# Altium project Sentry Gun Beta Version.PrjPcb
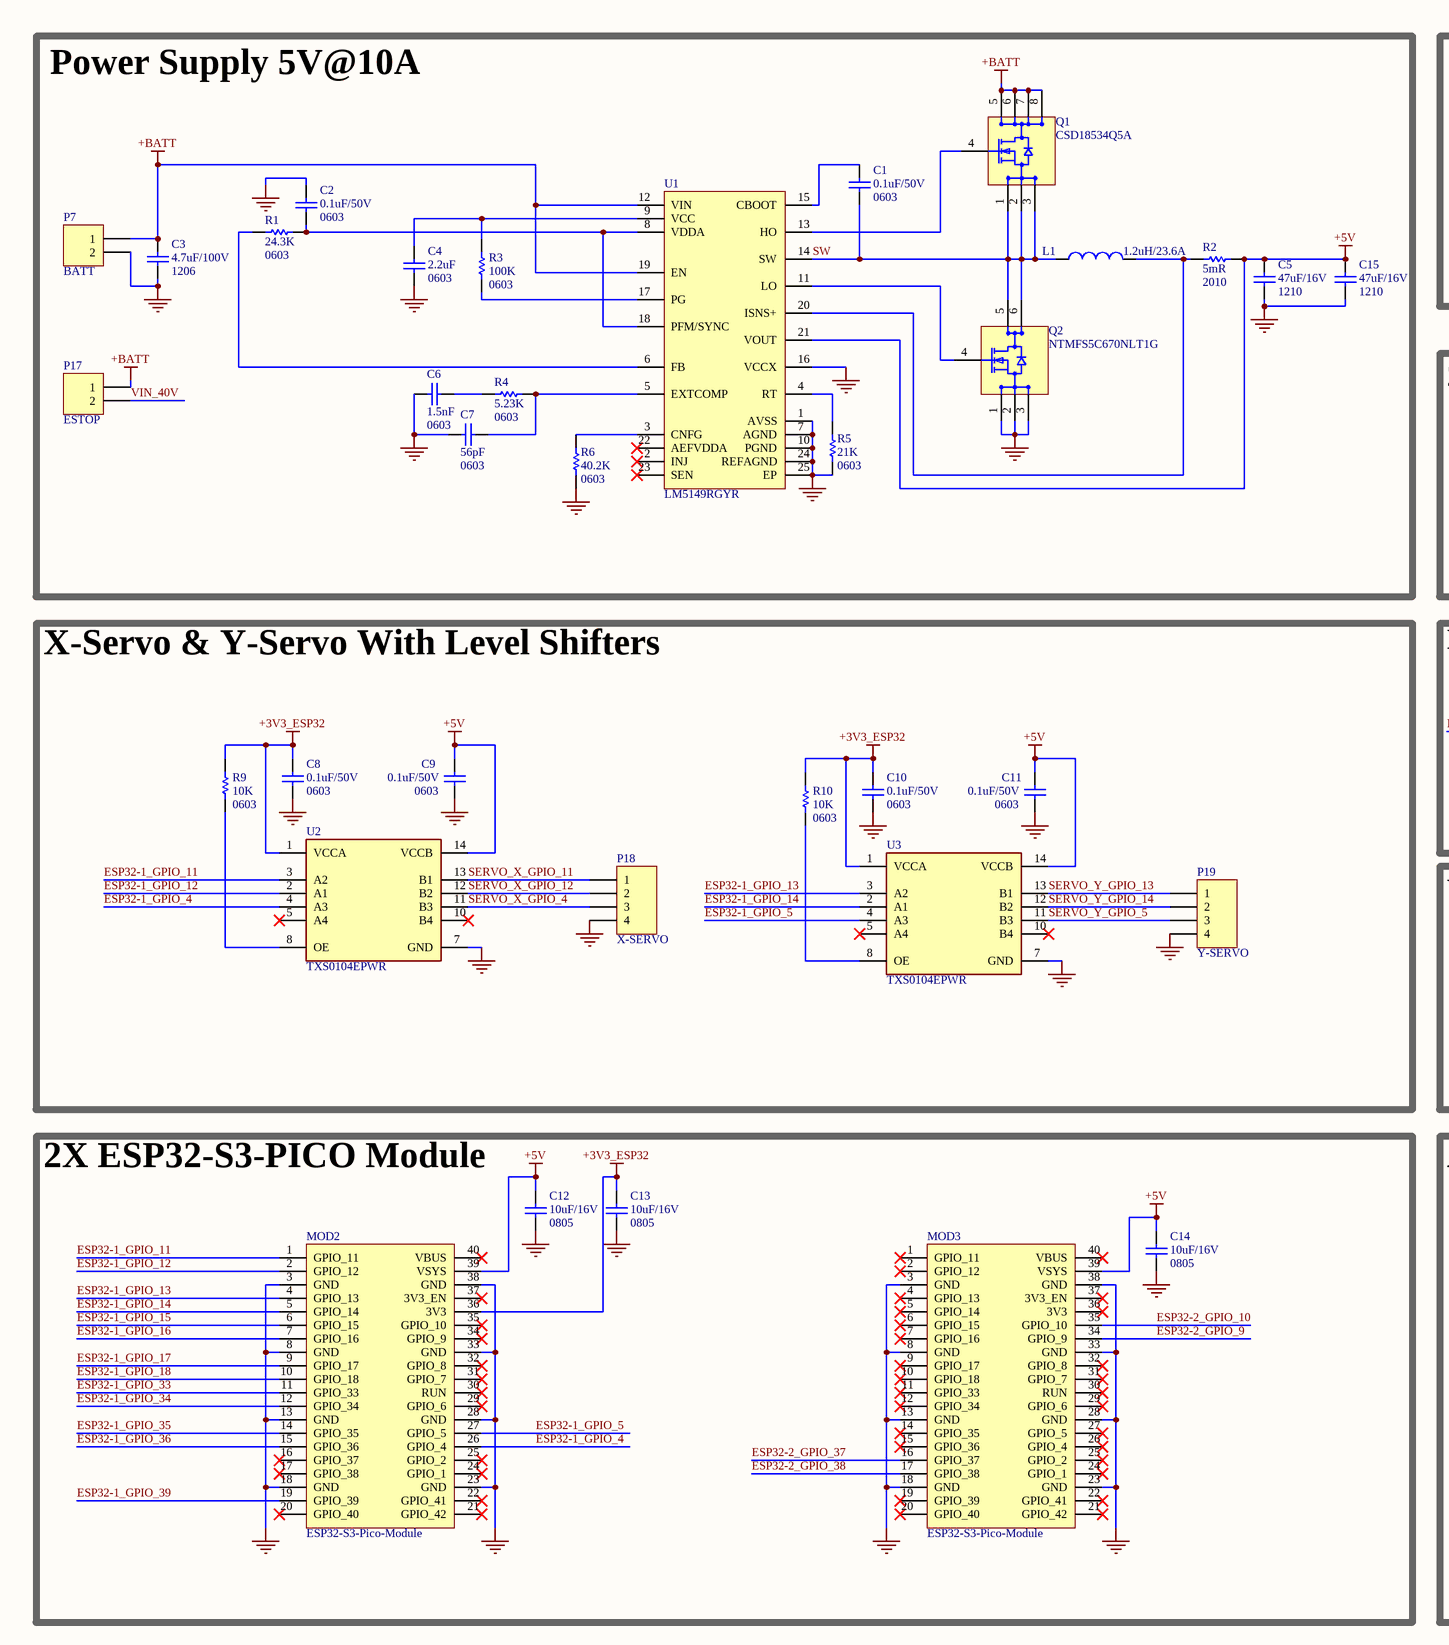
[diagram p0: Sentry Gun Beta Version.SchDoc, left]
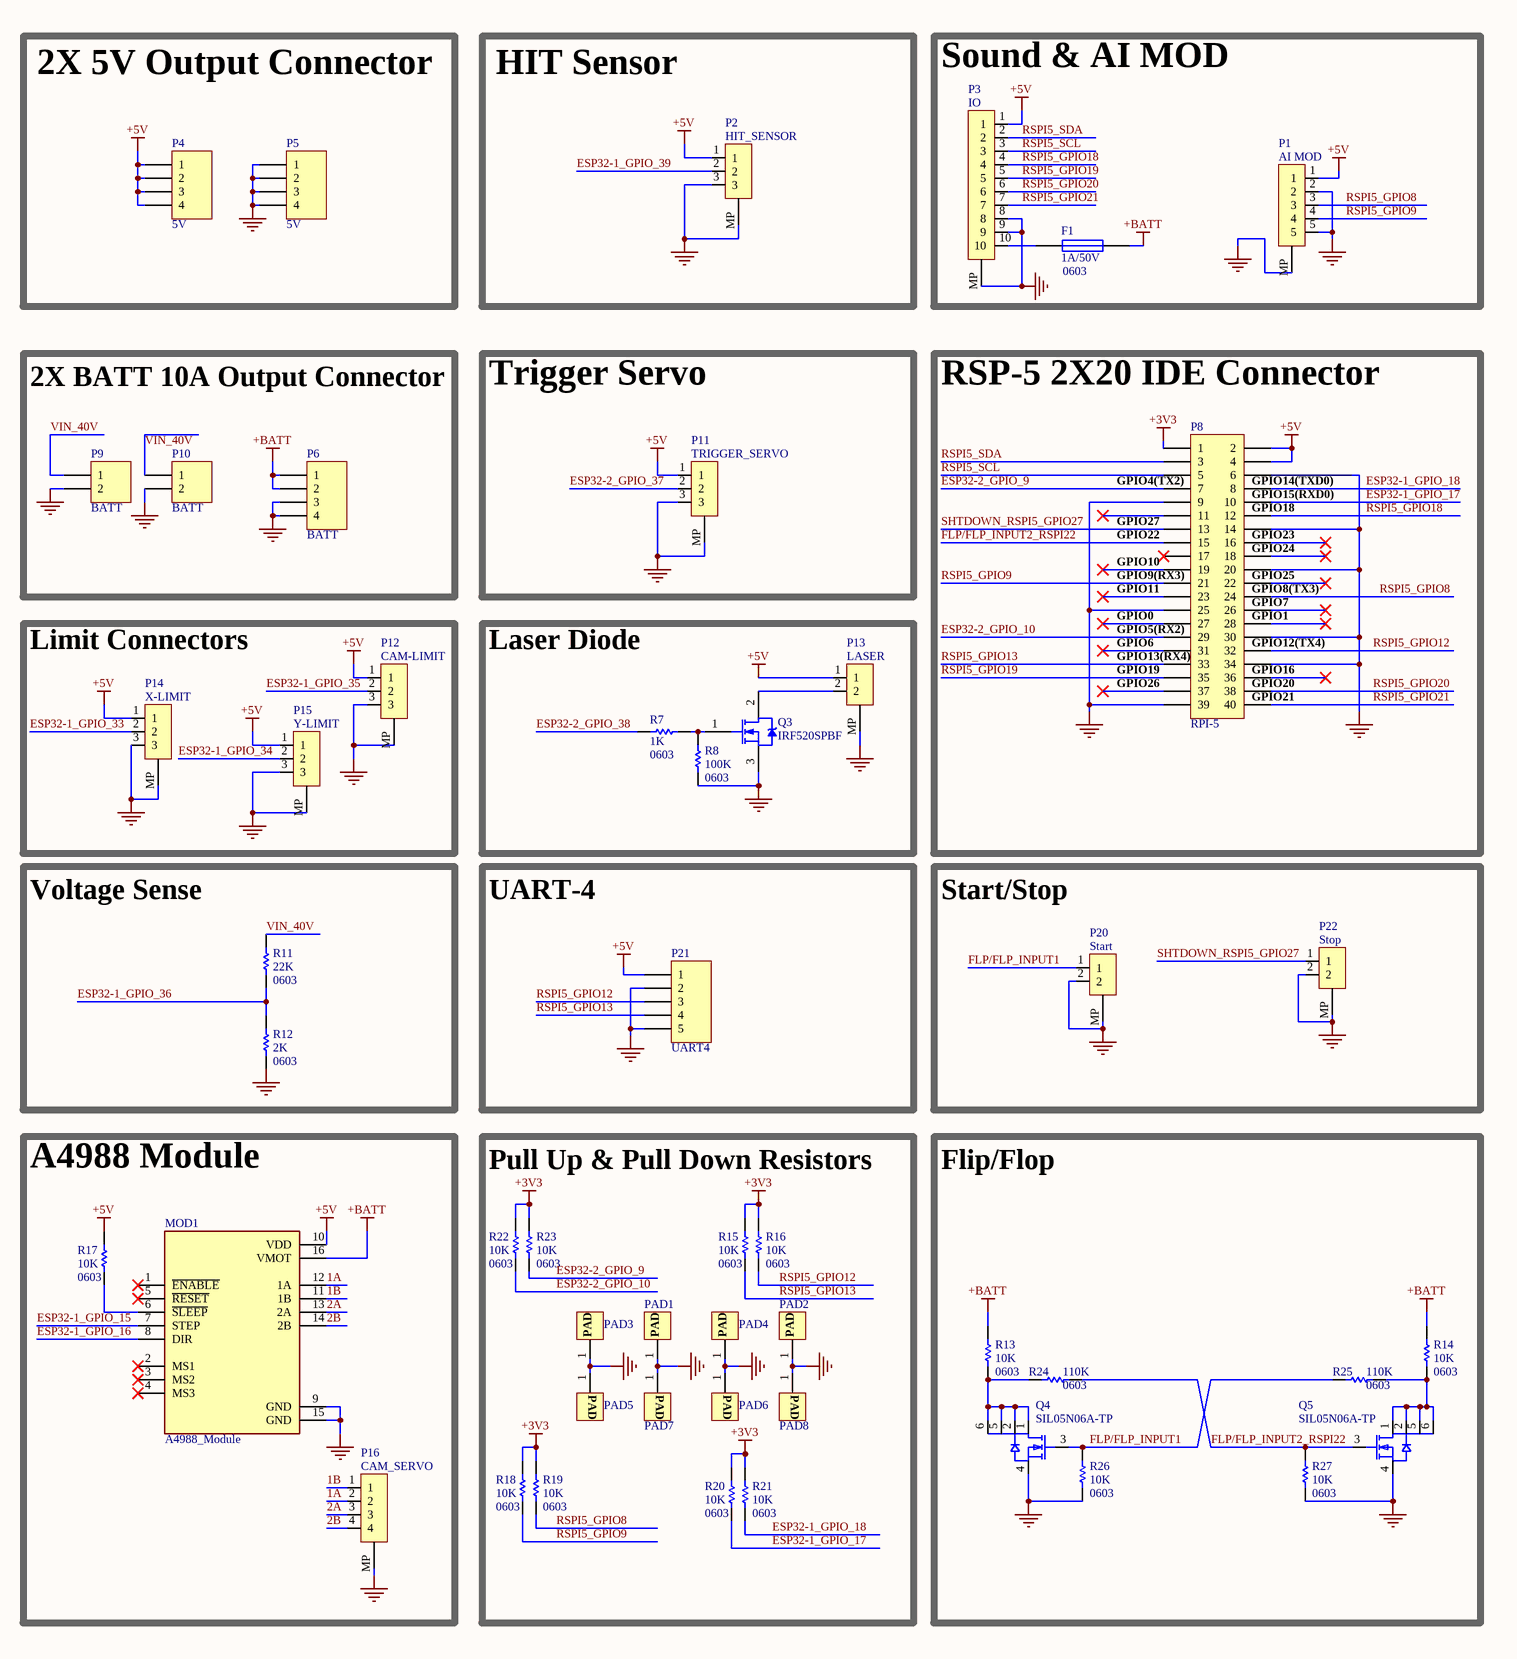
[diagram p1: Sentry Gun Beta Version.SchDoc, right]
1 sheet, 85 parts. Net scope: global (net labels, ports and power ports of the same name join across sheets).
Board file: PCB.PcbDoc

## Sheet Sentry Gun Beta Version.SchDoc
size A2; DocumentNumber: 0; SheetNumber: 0; SheetTotal: 7

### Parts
C1  0.1uF/50V  Package: 0603  [CAP_SMD_0603]
C2  0.1uF/50V  Package: 0603  [CAP_SMD_0603]
C3  4.7uF/100V  Package: 1206  [CAP_SMD_1206]
C4  2.2uF  Package: 0603  [CAP_SMD_0603]
C5  47uF/16V  Package: 1210  [CAP_SMD_1210]
C6  1.5nF  Package: 0603  [CAP_SMD_0603]
C7  56pF  Package: 0603  [CAP_SMD_0603]
C8  0.1uF/50V  Package: 0603  [CAP_SMD_0603]
C9  0.1uF/50V  Package: 0603  [CAP_SMD_0603]
C10  0.1uF/50V  Package: 0603  [CAP_SMD_0603]
C11  0.1uF/50V  Package: 0603  [CAP_SMD_0603]
C12  10uF/16V  Package: 0805  [CAP_SMD_0805]
C13  10uF/16V  Package: 0805  [CAP_SMD_0805]
C14  10uF/16V  Package: 0805  [CAP_SMD_0805]
C15  47uF/16V  Package: 1210  [CAP_SMD_1210]
F1  1A/50V  Package: 0603  [FUSE_SMD_0603]
L1  1.2uH/23.6A  [IND_SMD_7.90mm x 7.60mm]
MOD1  A4988_Module  [A4988_Stepper_Motor_Module]
MOD2  ESP32-S3-Pico-Module  [ESP32-S3-PICO_Module]
MOD3  ESP32-S3-Pico-Module  [ESP32-S3-PICO_Module]
P1  AI MOD  [CONN_Header_SMD_Vertical_5P_2MM_B5B-PH-SM4-TB]
P2  HIT_SENSOR  [CONN_Header_SMD_Vertical_3P_2MM_B3B-PH-SM4-TB]
P3  IO  [CONN_Header_SMD_Vertical_10P_2MM_B10B-PH-SM4-TB]
P4  5V  [CONN_Terminal_Block_Header_4P_Vertical__THT_5.00mm_1755532]
P5  5V  [CONN_Terminal_Block_Header_4P_Vertical__THT_5.00mm_1755532]
P6  BATT  [CONN_Terminal_Block_Header_4P_Vertical__THT_5.00mm_1755532]
P7  BATT  [CONN_HEADER_VERT_2POS_5MM_1-1376382-2]
P8  RPI-5  [CONN_HEADERTHT_IDE_40P_2.54mm]
P9  BATT  [CONN_HEADER_VERT_2POS_5MM_2-1376382-3]
P10  BATT  [CONN_HEADER_VERT_2POS_5MM_2-1376382-3]
P11  TRIGGER_SERVO  [CONN_Header_SMD_Vertical_3P_2MM_B3B-PH-SM4-TB]
P12  CAM-LIMIT  [CONN_Header_SMD_Vertical_3P_2MM_B3B-PH-SM4-TB]
P13  LASER  [CONN_Header_SMD_Vertical_2P_2MM_B2B-PH-SM4-TB]
P14  X-LIMIT  [CONN_Header_SMD_Vertical_3P_2MM_B3B-PH-SM4-TB]
P15  Y-LIMIT  [CONN_Header_SMD_Vertical_3P_2MM_B3B-PH-SM4-TB]
P16  CAM_SERVO  [CONN_Header_SMD_Vertical_4P_2MM_B4B-PH-SM4-TB]
P17  ESTOP  [CONN_HEADER_VERT_2POS_5MM_1-1376382-2]
P18  X-SERVO  [CONN_Header_Through_Hole_4P_2MM_B4B-PH-K]
P19  Y-SERVO  [CONN_Header_Through_Hole_4P_2MM_B4B-PH-K]
P20  Start  [CONN_Header_SMD_Vertical_2P_2MM_B2B-PH-SM4-TB]
P21  UART4  [CONN_Header_SMD_Vertical_5P_2MM_B5B-PH-SM4-TB]
P22  Stop  [CONN_Header_SMD_Vertical_2P_2MM_B2B-PH-SM4-TB]
PAD1  PAD  [PAD_SMD_0.8MMX0.9MM]  (value not drawn)
PAD2  PAD  [PAD_SMD_0.8MMX0.9MM]  (value not drawn)
PAD3  PAD  [PAD_SMD_0.8MMX0.9MM]  (value not drawn)
PAD4  PAD  [PAD_SMD_0.8MMX0.9MM]  (value not drawn)
PAD5  PAD  [PAD_SMD_0.8MMX0.9MM]  (value not drawn)
PAD6  PAD  [PAD_SMD_0.8MMX0.9MM]  (value not drawn)
PAD7  PAD  [PAD_SMD_0.8MMX0.9MM]  (value not drawn)
PAD8  PAD  [PAD_SMD_0.8MMX0.9MM]  (value not drawn)
Q1  CSD18534Q5A  [VSONP-8_5MMx6MM]
Q2  NTMFS5C670NLT1G  [DFN-5_5MMx6MM]
Q3  IRF520SPBF  [D2PAK]
Q4  SIL05N06A-TP  [SOT-23-6]
Q5  SIL05N06A-TP  [SOT-23-6]
R1  24.3K  Package: 0603  [RES_SMD_0603]
R2  5mR  Package: 2010  [RES_SMD_2010]
R3  100K  Package: 0603  [RES_SMD_0603]
R4  5.23K  Package: 0603  [RES_SMD_0603]
R5  21K  Package: 0603  [RES_SMD_0603]
R6  40.2K  Package: 0603  [RES_SMD_0603]
R7  1K  Package: 0603  [RES_SMD_0603]
R8  100K  Package: 0603  [RES_SMD_0603]
R9  10K  Package: 0603  [RES_SMD_0603]
R10  10K  Package: 0603  [RES_SMD_0603]
R11  22K  Package: 0603  [RES_SMD_0603]
R12  2K  Package: 0603  [RES_SMD_0603]
R13  10K  Package: 0603  [RES_SMD_0603]
R14  10K  Package: 0603  [RES_SMD_0603]
R15  10K  Package: 0603  [RES_SMD_0603]
R16  10K  Package: 0603  [RES_SMD_0603]
R17  10K  Package: 0603  [RES_SMD_0603]
R18  10K  Package: 0603  [RES_SMD_0603]
R19  10K  Package: 0603  [RES_SMD_0603]
R20  10K  Package: 0603  [RES_SMD_0603]
R21  10K  Package: 0603  [RES_SMD_0603]
R22  10K  Package: 0603  [RES_SMD_0603]
R23  10K  Package: 0603  [RES_SMD_0603]
R24  110K  Package: 0603  [RES_SMD_0603]
R25  110K  Package: 0603  [RES_SMD_0603]
R26  10K  Package: 0603  [RES_SMD_0603]
R27  10K  Package: 0603  [RES_SMD_0603]
U1  LM5149RGYR  [VQFN-24_3.5MMx5.5MM]
U2  TXS0104EPWR  [TSSOP-14]
U3  TXS0104EPWR  [TSSOP-14]

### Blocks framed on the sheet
Power Supply 5V@10A: C1-C7 C15 L1 P7 P17 Q1 Q2 R1-R6 U1
2X 5V Output Connector: P4 P5
HIT Sensor: P2
Sound & AI MOD: F1 P1 P3
2X BATT 10A Output Connector: P6 P9 P10
Trigger Servo: P11
RSP-5 2X20 IDE Connector: P8
X-Servo & Y-Servo With Level Shifters: C8-C11 P18 P19 R9 R10 U2 U3
Limit Connectors: P12 P14 P15
Laser Diode: P13 Q3 R7 R8
Voltage Sense: R11 R12
UART-4: P21
Start/Stop: P20 P22
2X ESP32-S3-PICO Module: C12-C14 MOD2 MOD3
A4988 Module: MOD1 P16 R17
Pull Up & Pull Down Resistors: PAD1-PAD8 R15 R16 R18-R23
Flip/Flop: Q4 Q5 R13 R14 R24-R27

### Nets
+3V3: P8.1 R15.2 R16.2 R18.2 R19.2 R20.2 R21.2 R22.2 R23.2
+3V3_ESP32: C8.2 C10.2 C13.2 MOD2.36(3V3) R9.2 R10.2 U2.1(VCCA) U3.1(VCCA)
+5V: C5.2 C9.2 C11.2 C12.2 C14.2 C15.2 MOD1.10(VDD) MOD2.39(VSYS) MOD3.39(VSYS) P1.1 P2.1 P3.1 P4.1 P4.2 P4.3 P4.4 P8.2 P8.4 P11.1 P12.1 P13.1 P14.1 P15.1 P21.1 R2.2 R17.2 U1.21(VOUT) U2.14(VCCB) U3.14(VCCB)
+BATT: C3.2 F1.2 MOD1.16(VMOT) P6.1 P6.2 P7.1 P17.1 Q1.5(D_1) Q1.6(D_2) Q1.7(D_3) Q1.8(D_4) R13.2 R14.2 U1.12(VIN) U1.19(EN)
GND: C2.2 C3.1 C4.1 C5.1 C6.2 C7.2 C8.1 C9.1 C10.1 C11.1 C12.1 C13.1 C14.1 C15.1 MOD1.9(GND) MOD1.15(GND) MOD2.3(GND) MOD2.8(GND) MOD2.13(GND) MOD2.18(GND) MOD2.23(GND) MOD2.28(GND) MOD2.33(GND) MOD2.38(GND) MOD3.3(GND) MOD3.8(GND) MOD3.13(GND) MOD3.18(GND) MOD3.23(GND) MOD3.28(GND) MOD3.33(GND) MOD3.38(GND) P1.2 P1.5 P1.MP P2.3 P2.MP P3.8 P3.9 P3.MP P5.1 P5.2 P5.3 P5.4 P6.3 P6.4 P7.2 P8.6 P8.9 P8.14 P8.20 P8.25 P8.30 P8.34 P8.39 P9.2 P10.2 P11.3 P11.MP P12.3 P12.MP P13.MP P14.3 P14.MP P15.3 P15.MP P16.MP P18.4 P19.4 P20.2 P20.MP P21.2 P21.5 P22.2 P22.MP PAD1.1 PAD2.1 PAD3.1 PAD4.1 PAD5.1 PAD6.1 PAD7.1 PAD8.1 Q2.1(S_1) Q2.2(S_2) Q2.3(S_3) Q3.3(S) Q4.4(S) Q5.4(S) R5.2 R6.2 R8.1 R12.1 R26.1 R27.1 U1.1(AVSS) U1.7(AGND) U1.10(PGND) U1.16(VCCX) U1.24(REFAGND) U1.25(EP) U2.7(GND) U3.7(GND)
1A: MOD1.12(1A) P16.2
1B: MOD1.11(1B) P16.1
2A: MOD1.13(2A) P16.3
2B: MOD1.14(2B) P16.4
ESP32-1_GPIO_4: MOD2.26(GPIO_4) U2.4(A3)
ESP32-1_GPIO_5: MOD2.27(GPIO_5) U3.4(A3)
ESP32-1_GPIO_11: MOD2.1(GPIO_11) U2.3(A2)
ESP32-1_GPIO_12: MOD2.2(GPIO_12) U2.2(A1)
ESP32-1_GPIO_13: MOD2.4(GPIO_13) U3.3(A2)
ESP32-1_GPIO_14: MOD2.5(GPIO_14) U3.2(A1)
ESP32-1_GPIO_15: MOD1.7(STEP) MOD2.6(GPIO_15)
ESP32-1_GPIO_16: MOD1.8(DIR) MOD2.7(GPIO_16)
ESP32-1_GPIO_17: MOD2.9(GPIO_17) P8.10 R20.1
ESP32-1_GPIO_18: MOD2.10(GPIO_18) P8.8 R21.1
ESP32-1_GPIO_33: MOD2.11(GPIO_33) P14.2
ESP32-1_GPIO_34: MOD2.12(GPIO_34) P15.2
ESP32-1_GPIO_35: MOD2.14(GPIO_35) P12.2
ESP32-1_GPIO_36: MOD2.15(GPIO_36) R11.1 R12.2
ESP32-1_GPIO_39: MOD2.19(GPIO_39) P2.2
ESP32-2_GPIO_9: MOD3.34(GPIO_9) P8.7 R23.1
ESP32-2_GPIO_10: MOD3.35(GPIO_10) P8.29 R22.1
ESP32-2_GPIO_37: MOD3.16(GPIO_37) P11.2
ESP32-2_GPIO_38: MOD3.17(GPIO_38) R7.2
FLP/FLP_INPUT1: P20.1 Q4.3(G) R25.2 R26.2
FLP/FLP_INPUT2_RSPI22: P8.15 Q5.3(G) R24.1 R27.2
RSPI5_GPIO8: P1.3 P8.24 R19.1
RSPI5_GPIO9: P1.4 P8.21 R18.1
RSPI5_GPIO12: P8.32 P21.3 R16.1
RSPI5_GPIO13: P8.33 P21.4 R15.1
RSPI5_GPIO18: P3.4 P8.12
RSPI5_GPIO19: P3.5 P8.35
RSPI5_GPIO20: P3.6 P8.38
RSPI5_GPIO21: P3.7 P8.40
RSPI5_SCL: P3.3 P8.5
RSPI5_SDA: P3.2 P8.3
SERVO_X_GPIO_4: P18.3 U2.11(B3)
SERVO_X_GPIO_11: P18.1 U2.13(B1)
SERVO_X_GPIO_12: P18.2 U2.12(B2)
SERVO_Y_GPIO_5: P19.3 U3.11(B3)
SERVO_Y_GPIO_13: P19.1 U3.13(B1)
SERVO_Y_GPIO_14: P19.2 U3.12(B2)
SHTDOWN_RSPI5_GPIO27: P8.13 P22.1
SW: C1.1 L1.1 Q1.1(S_1) Q1.2(S_2) Q1.3(S_3) Q2.5(D_1) Q2.6(D_2) U1.14(SW)
VIN_40V: P9.1 P10.1 P17.2 R11.2
NetC1_2: C1.2 U1.15(CBOOT)
NetC2_1: C2.1 R1.1 U1.8(VDDA) U1.18(PFM/SYNC)
NetC4_2: C4.2 R3.2 U1.9(VCC)
NetC6_1: C6.1 R4.2
NetC7_1: C7.1 R4.1 U1.5(EXTCOMP)
NetF1_1: F1.1 P3.10
NetL1_2: L1.2 R2.1 U1.20(ISNS+)
NetMOD1_6: MOD1.6(~{SLEEP}) R17.1
NetP13_2: P13.2 Q3.2(D)
NetQ1_4: Q1.4(G) U1.13(HO)
NetQ2_4: Q2.4(G) U1.11(LO)
NetQ3_1: Q3.1(G) R7.1 R8.2
NetQ4_1: Q4.1(D) Q4.2(D) Q4.5(D) Q4.6(D) R13.1 R24.2
NetQ5_1: Q5.1(D) Q5.2(D) Q5.5(D) Q5.6(D) R14.1 R25.1
NetR1_2: R1.2 U1.6(FB)
NetR3_1: R3.1 U1.17(PG)
NetR5_1: R5.1 U1.4(RT)
NetR6_1: R6.1 U1.3(CNFG)
NetR9_1: R9.1 U2.8(OE)
NetR10_1: R10.1 U3.8(OE)

Not connected (* = marked no-connect by the designer): MOD1 1(~{ENABLE})* 2(MS1)* 3(MS2)* 4(MS3)* 5(~{RESET})*; MOD2 16(GPIO_37)* 17(GPIO_38)* 20(GPIO_40)* 21(GPIO_42)* 22(GPIO_41)* 24(GPIO_1)* 25(GPIO_2)* 29(GPIO_6)* 30(RUN)* 31(GPIO_7)* 32(GPIO_8)* 34(GPIO_9)* 35(GPIO_10)* 37(3V3_EN)* 40(VBUS)*; MOD3 1(GPIO_11)* 2(GPIO_12)* 4(GPIO_13)* 5(GPIO_14)* 6(GPIO_15)* 7(GPIO_16)* 9(GPIO_17)* 10(GPIO_18)* 11(GPIO_33)* 12(GPIO_34)* 14(GPIO_35)* 15(GPIO_36)* 19(GPIO_39)* 20(GPIO_40)* 21(GPIO_42)* 22(GPIO_41)* 24(GPIO_1)* 25(GPIO_2)* 26(GPIO_4)* 27(GPIO_5)* 29(GPIO_6)* 30(RUN)* 31(GPIO_7)* 32(GPIO_8)* 36(3V3)* 37(3V3_EN)* 40(VBUS)*; P8 11* 16* 17* 18* 19* 22* 23* 26* 27* 28* 31* 36* 37*; U1 2(INJ)* 22(AEFVDDA)* 23(SEN)*; U2 5(A4)* 10(B4)*; U3 5(A4)* 10(B4)*

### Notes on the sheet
- (near P8) GPIO4(TX2)
- (near P8) GPIO14(TXD0)
- (near P8) GPIO15(RXD0)
- (near P8) GPIO10
- (near P8) GPIO27
- (near P8) GPIO22
- (near P8) GPIO18
- (near P8) GPIO23
- (near P8) GPIO24
- (near P8) GPIO5(RX2)
- (near P8) GPIO9(RX3)
- (near P8) GPIO0
- (near P8) GPIO11
- (near P8) GPIO8(TX3)
- (near P8) GPIO25
- (near P8) GPIO7
- (near P8) GPIO1
- (near P8) GPIO13(RX4)
- (near P8) GPIO6
- (near P8) GPIO26
- (near P8) GPIO19
- (near P8) GPIO12(TX4)
- (near P8) GPIO16
- (near P8) GPIO20
- (near P8) GPIO21

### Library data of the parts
C1-C15 = Cap: Capacitor
F1 = Fuse 1: Fuse
L1 = Inductor
MOD1 = A4988_STEPPER_MOTOR_DRIVER_CARRIER
P1 = HEADER 5X SMT
P2 P11 P12 P14 P15 = HEADER 3X SMT
P3 = HEADER 10X SMT
P4-P6 P18 P19 = Header 4: Header, 4-Pin
P7 P9 P10 P17 = Header 2: Header, 2-Pin
P8 = Header 20X2: Header, 20-Pin, Dual row
P13 P20 P22 = HEADER 2X SMT
P16 = HEADER 4X SMT
P21 = Header 5: Header, 5-Pin
Q3 = NMOS-2: N-Channel Power MOSFET
R1-R27 = Res1: Resistor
